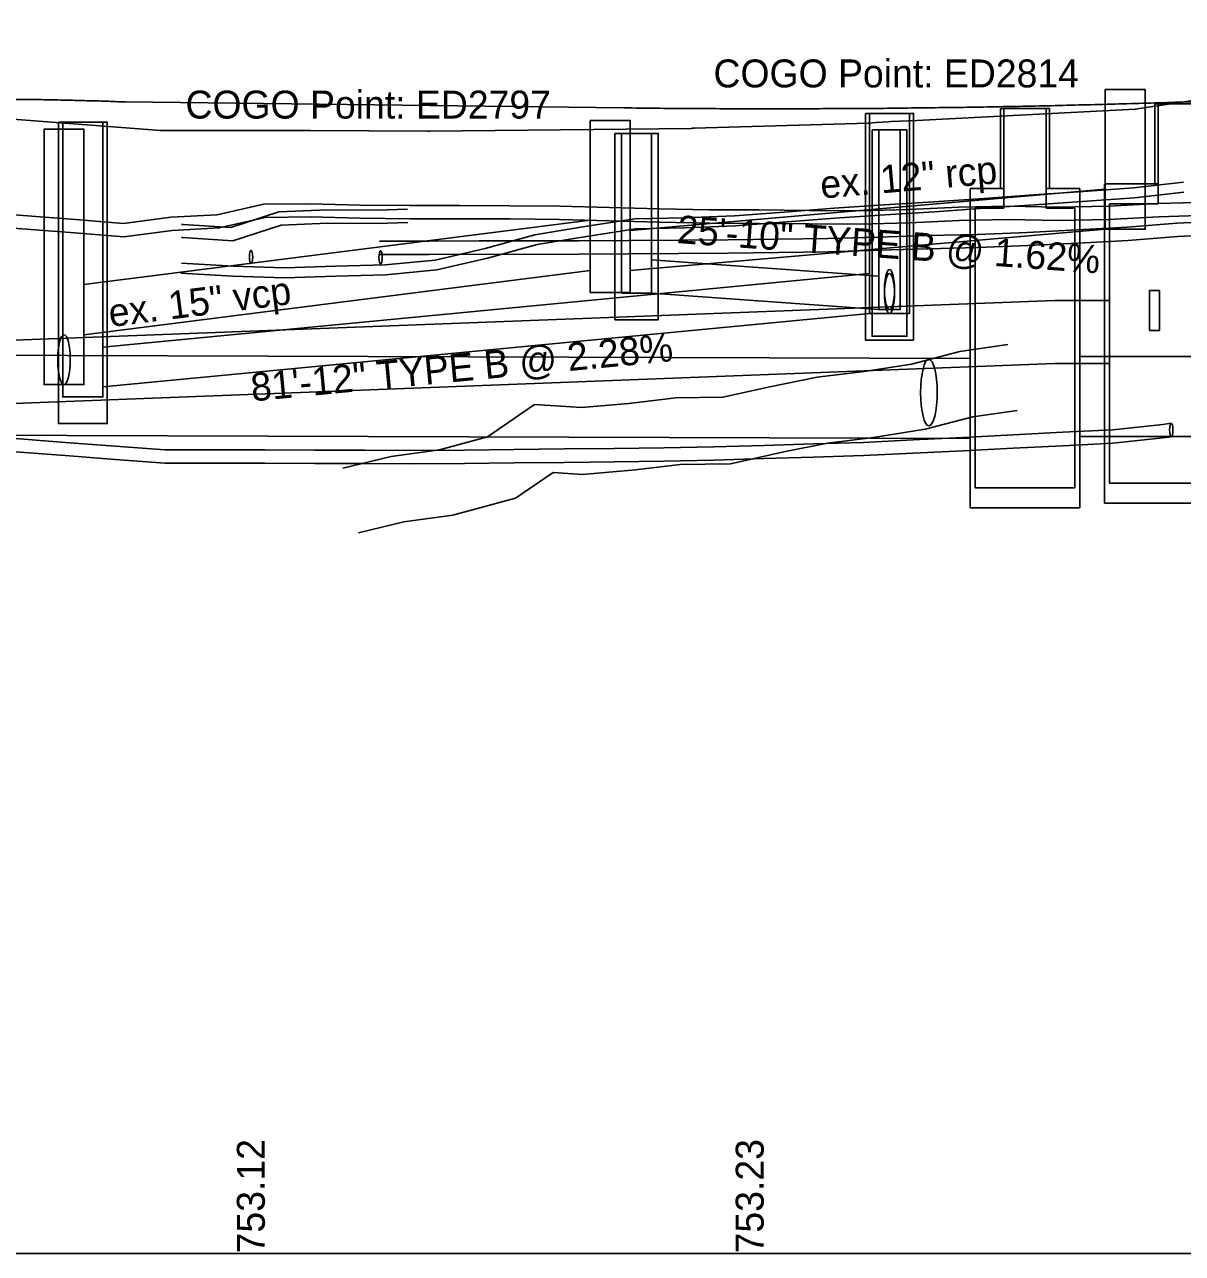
# Model space of a CAD drawing. Extents: x 1833473 to 1837132, y 704683 to 706683.
# Drawn here: x 1834036.7 to 1834152.8, y 705682.6 to 705805.8 of the extents above; entities that cross this region are included whole.
import ezdxf

# ---------------------------------------------------------------- set-up
doc = ezdxf.new("R2010")
doc.units = 0
for name, color, linetype in [('DR_P_Text', 7, 'Continuous'), ('DR_X_Cells', 7, 'Continuous'), ('DR_X_Storm_Sewer', 7, 'Continuous'), ('DR_X_Text', 7, 'Continuous'), ('GK_Cells', 7, 'Continuous'), ('PF_P_Grade_Line', 7, 'Continuous'), ('PF_X_Ground_Line', 7, 'Continuous'), ('PF_X_Text', 7, 'Continuous'), ('SC_Scratch1', 7, 'Continuous'), ('UT_P_Electric', 7, 'Continuous'), ('UT_P_Telecom', 7, 'Continuous'), ('UT_X_Electric', 7, 'Continuous'), ('UT_X_Gas', 7, 'Continuous'), ('UT_X_Water', 7, 'Continuous')]:
    doc.layers.add(name, color=color, linetype=linetype)

msp = doc.modelspace()

# ---------------------------------------------------------------- linework, layer by layer
at = {"layer": 'DR_X_Cells'}
for points in [[(1834035.78, 705764.29), (1834040.78, 705763.9), (1834045.78, 705763.51), (1834050.78, 705763.15), (1834055.78, 705763.15), (1834060.78, 705763.14), (1834065.78, 705763.12), (1834070.78, 705763.11), (1834075.78, 705763.09), (1834080.78, 705763.13), (1834085.78, 705763.18), (1834090.78, 705763.24), (1834095.78, 705763.29), (1834100.78, 705763.34), (1834105.78, 705763.45), (1834110.78, 705763.6), (1834115.78, 705763.75), (1834120.78, 705763.9), (1834125.78, 705764.14), (1834130.78, 705764.4), (1834135.78, 705764.65), (1834140.78, 705764.91), (1834145.78, 705765.16), (1834150.78, 705765.7), (1834151.63, 705765.81)], [(1834035.78, 705762.95), (1834040.78, 705762.57), (1834045.78, 705762.18), (1834050.78, 705761.82), (1834055.78, 705761.82), (1834060.78, 705761.81), (1834065.78, 705761.79), (1834070.78, 705761.77), (1834075.78, 705761.75), (1834080.78, 705761.8), (1834085.78, 705761.85), (1834090.78, 705761.9), (1834095.78, 705761.96), (1834100.78, 705762.01), (1834105.78, 705762.11), (1834110.78, 705762.27), (1834115.78, 705762.42), (1834120.78, 705762.57), (1834125.78, 705762.81), (1834130.78, 705763.06), (1834135.78, 705763.32), (1834140.78, 705763.57), (1834145.78, 705763.83), (1834150.78, 705764.36), (1834151.63, 705764.47)]]:
    msp.add_lwpolyline(points, dxfattribs=at)
msp.add_ellipse((1834151.63, 705765.14), major_axis=(0, 0.667), ratio=0.25, dxfattribs=at)
at = {"layer": 'DR_X_Storm_Sewer'}
for p, q in [((1834042.54, 705795.97), (1834042.54, 705795.97)), ((1834097.4, 705785.14), (1834145.02, 705789.26)), ((1834042.65, 705779.73), (1834093.4, 705786.17)), ((1834097.4, 705781.13), (1834145.02, 705785.25)), ((1834099.54, 705782.18), (1834122.31, 705780.54)), ((1834042.65, 705774.69), (1834093.4, 705781.13)), ((1834121.39, 705780.81), (1834044.56, 705773.45)), ((1834099.54, 705778.85), (1834122.31, 705777.21)), ((1834121.39, 705776.81), (1834044.56, 705769.45))]:
    msp.add_line(p, q, dxfattribs=at)
for points in [[(1834147.02, 705799.25), (1834145.02, 705799.25), (1834145.02, 705785.25), (1834149.02, 705785.25), (1834149.02, 705799.25), (1834147.02, 705799.25)], [(1834120.97, 705796.85), (1834120.97, 705774.14), (1834125.81, 705774.14), (1834125.81, 705796.85), (1834120.97, 705796.85)], [(1834121.39, 705796.85), (1834121.39, 705776.81), (1834125.39, 705776.81), (1834125.39, 705796.85)], [(1834040.65, 705795.29), (1834038.65, 705795.29), (1834038.65, 705769.69), (1834042.65, 705769.69), (1834042.65, 705795.29), (1834040.65, 705795.29)], [(1834040.1, 705795.97), (1834040.1, 705765.78), (1834044.98, 705765.78), (1834044.98, 705795.97), (1834040.1, 705795.97)], [(1834040.52, 705795.97), (1834040.52, 705768.45), (1834044.56, 705768.45), (1834044.56, 705795.97)], [(1834095.4, 705796.13), (1834093.4, 705796.13), (1834093.4, 705778.93), (1834097.4, 705778.93), (1834097.4, 705796.13), (1834095.4, 705796.13)], [(1834121.64, 705795.21), (1834121.64, 705774.54), (1834125.14, 705774.54), (1834125.14, 705795.21), (1834121.64, 705795.21)], [(1834122.31, 705795.21), (1834122.31, 705777.21), (1834124.47, 705777.21), (1834124.47, 705795.21)], [(1834095.87, 705794.85), (1834095.87, 705776.18), (1834100.21, 705776.18), (1834100.21, 705794.85), (1834095.87, 705794.85)], [(1834096.54, 705794.85), (1834096.54, 705778.85), (1834099.54, 705778.85), (1834099.54, 705794.85)]]:
    msp.add_lwpolyline(points, dxfattribs=at)
for centre, major_axis in [((1834123.39, 705779.21), (0, 2)), ((1834123.39, 705778.81), (0, 2)), ((1834040.65, 705772.19), (0, 2.5))]:
    msp.add_ellipse(centre, major_axis=major_axis, ratio=0.25, dxfattribs=at)
at = {"layer": 'GK_Cells'}
msp.add_line((1833710.78, 705682.65), (1834910.78, 705682.65), dxfattribs=at)
msp.add_line((1833710.78, 705682.65), (1834910.78, 705682.65), dxfattribs=at)
at = {"layer": 'PF_P_Grade_Line'}
msp.add_line((1834046.78, 705798.01), (1834096.78, 705797.41), dxfattribs=at)
for points in [[(1834096.78, 705797.41), (1834099.98, 705797.37), (1834103.18, 705797.35), (1834106.38, 705797.33), (1834109.58, 705797.32), (1834112.78, 705797.32), (1834115.98, 705797.33), (1834119.18, 705797.34), (1834122.38, 705797.36), (1834125.58, 705797.4), (1834128.78, 705797.44), (1834131.98, 705797.48), (1834135.18, 705797.54), (1834138.38, 705797.6), (1834141.58, 705797.68), (1834144.78, 705797.76), (1834147.98, 705797.85), (1834151.18, 705797.94), (1834154.38, 705798.05), (1834157.58, 705798.16), (1834160.78, 705798.28), (1834163.98, 705798.41), (1834167.18, 705798.55), (1834170.38, 705798.7), (1834173.58, 705798.85), (1834176.78, 705799.02), (1834179.98, 705799.19), (1834183.18, 705799.37), (1834186.38, 705799.55), (1834189.58, 705799.75), (1834192.78, 705799.95), (1834195.98, 705800.16), (1834199.18, 705800.39), (1834202.38, 705800.61), (1834205.58, 705800.85), (1834208.78, 705801.1), (1834211.98, 705801.35), (1834215.18, 705801.61), (1834218.38, 705801.88), (1834221.58, 705802.16), (1834224.78, 705802.44), (1834227.98, 705802.74), (1834231.18, 705803.04), (1834234.38, 705803.35), (1834237.58, 705803.67), (1834240.78, 705804), (1834243.98, 705804.33), (1834247.18, 705804.68), (1834250.38, 705805.03), (1834253.58, 705805.39), (1834256.78, 705805.76)], [(1833998.78, 705796.77), (1833999.74, 705796.85), (1834000.7, 705796.94), (1834001.66, 705797.02), (1834002.62, 705797.09), (1834003.58, 705797.17), (1834004.54, 705797.24), (1834005.5, 705797.31), (1834006.46, 705797.38), (1834007.42, 705797.44), (1834008.38, 705797.51), (1834009.34, 705797.57), (1834010.3, 705797.62), (1834011.26, 705797.68), (1834012.22, 705797.73), (1834013.18, 705797.78), (1834014.14, 705797.83), (1834015.1, 705797.88), (1834016.06, 705797.92), (1834017.02, 705797.96), (1834017.98, 705798), (1834018.94, 705798.03), (1834019.9, 705798.07), (1834020.86, 705798.1), (1834021.82, 705798.13), (1834022.78, 705798.15), (1834023.74, 705798.18), (1834024.7, 705798.2), (1834025.66, 705798.22), (1834026.62, 705798.23), (1834027.58, 705798.25), (1834028.54, 705798.26), (1834029.5, 705798.27), (1834030.46, 705798.27), (1834031.42, 705798.28), (1834032.38, 705798.28), (1834033.34, 705798.28), (1834034.3, 705798.28), (1834035.26, 705798.27), (1834036.22, 705798.26), (1834037.18, 705798.25), (1834038.14, 705798.24), (1834039.1, 705798.22), (1834040.06, 705798.2), (1834041.02, 705798.18), (1834041.98, 705798.16), (1834042.94, 705798.13), (1834043.9, 705798.11), (1834044.86, 705798.08), (1834045.82, 705798.04), (1834046.78, 705798.01)]]:
    msp.add_spline(points, degree=3, dxfattribs=at)
at = {"layer": 'PF_X_Ground_Line'}
msp.add_lwpolyline([(1834023.29, 705797.22), (1834050.31, 705795.15), (1834050.32, 705795.15), (1834050.34, 705795.15), (1834050.36, 705795.15), (1834050.38, 705795.15), (1834050.39, 705795.15), (1834050.4, 705795.15), (1834050.41, 705795.15), (1834050.43, 705795.15), (1834050.46, 705795.15), (1834050.49, 705795.15), (1834050.52, 705795.15), (1834050.54, 705795.15), (1834065.28, 705795.13), (1834077.13, 705795.08), (1834077.14, 705795.08), (1834077.15, 705795.08), (1834077.17, 705795.08), (1834077.19, 705795.08), (1834077.21, 705795.08), (1834077.24, 705795.08), (1834077.27, 705795.09), (1834077.3, 705795.09), (1834077.32, 705795.09), (1834103.54, 705795.36), (1834103.58, 705795.37), (1834103.7, 705795.37), (1834103.82, 705795.38), (1834121.28, 705795.89), (1834122.04, 705795.94), (1834123.26, 705796.01), (1834123.57, 705796.03), (1834124.38, 705796.07), (1834126.12, 705796.16), (1834148, 705797.28), (1834154.25, 705798.22)], dxfattribs=at)
at = {"layer": 'UT_P_Electric'}
for p, q in [((1834149.99, 705789.8), (1834149.99, 705797.8)), ((1834149.99, 705797.8), (1834154.91, 705797.8)), ((1834150.32, 705787.8), (1834150.32, 705797.8)), ((1834144.95, 705757.8), (1834144.95, 705789.8)), ((1834144.95, 705789.8), (1834150.32, 705789.8)), ((1834145.45, 705759.8), (1834145.45, 705787.8)), ((1834145.45, 705787.8), (1834150.32, 705787.8)), ((1834150.45, 705779.12), (1834149.44, 705779.12)), ((1834149.44, 705775.12), (1834149.44, 705779.12)), ((1834150.45, 705779.12), (1834150.45, 705775.12)), ((1833958.33, 705771.16), (1834139.95, 705778.12)), ((1834145.45, 705778.12), (1834139.95, 705778.12)), ((1834150.45, 705775.12), (1834149.44, 705775.12)), ((1833958.33, 705764.83), (1834139.95, 705771.79)), ((1834145.45, 705771.79), (1834139.95, 705771.79)), ((1834159.45, 705759.8), (1834145.45, 705759.8)), ((1834159.95, 705757.8), (1834144.95, 705757.8))]:
    msp.add_line(p, q, dxfattribs=at)
at = {"layer": 'UT_P_Telecom'}
for p, q in [((1834134.51, 705789.35), (1834134.51, 705797.35)), ((1834134.51, 705797.35), (1834139.43, 705797.35)), ((1834134.84, 705787.35), (1834134.84, 705797.35)), ((1834139.09, 705787.35), (1834139.09, 705797.35)), ((1834139.43, 705789.35), (1834139.43, 705797.35)), ((1834131.47, 705757.35), (1834131.47, 705789.35)), ((1834131.47, 705789.35), (1834134.84, 705789.35)), ((1834139.09, 705789.35), (1834142.47, 705789.35)), ((1834142.47, 705789.35), (1834142.47, 705757.35)), ((1834131.97, 705759.35), (1834131.97, 705787.35)), ((1834131.97, 705787.35), (1834134.84, 705787.35)), ((1834139.09, 705787.35), (1834141.97, 705787.35)), ((1834141.97, 705787.35), (1834141.97, 705759.35)), ((1834142.47, 705772.5), (1834175.78, 705772.5)), ((1834142.47, 705764.5), (1834175.78, 705764.5)), ((1834141.97, 705759.35), (1834131.97, 705759.35)), ((1834142.47, 705757.35), (1834131.47, 705757.35))]:
    msp.add_line(p, q, dxfattribs=at)
for points in [[(1833910.78, 705760.34), (1834010.78, 705772.69), (1834131.47, 705772.3)], [(1833910.78, 705752.34), (1834010.78, 705764.69), (1834131.47, 705764.3)]]:
    msp.add_lwpolyline(points, dxfattribs=at)
at = {"layer": 'UT_X_Electric'}
for points in [[(1834032.22, 705786.96), (1834037.01, 705786.59), (1834041.81, 705786.22), (1834046.61, 705785.82), (1834051.35, 705786.45), (1834056.02, 705786.71), (1834060.65, 705787.77), (1834065.34, 705787.81), (1834070.34, 705787.68), (1834075.34, 705787.63), (1834080.34, 705787.63), (1834085.34, 705787.61), (1834090.34, 705787.56), (1834095.34, 705787.43), (1834100.34, 705787.29), (1834105.34, 705787.2), (1834110.34, 705787.18), (1834115.34, 705787.13), (1834120.34, 705787.09), (1834125.34, 705787.22), (1834130.34, 705787.47), (1834135.33, 705787.55), (1834140.33, 705787.47), (1834145.33, 705787.57), (1834150.32, 705787.83), (1834155.32, 705787.98)], [(1834032.12, 705785.63), (1834036.91, 705785.26), (1834041.7, 705784.9), (1834046.64, 705784.48), (1834051.48, 705785.13), (1834056.21, 705785.38), (1834060.81, 705786.44), (1834065.33, 705786.48), (1834070.32, 705786.35), (1834075.34, 705786.3), (1834080.34, 705786.3), (1834085.33, 705786.28), (1834090.32, 705786.23), (1834100.31, 705785.96), (1834105.33, 705785.87), (1834110.33, 705785.84), (1834120.35, 705785.76), (1834125.39, 705785.89), (1834130.38, 705786.13), (1834135.33, 705786.22), (1834140.33, 705786.13), (1834145.38, 705786.24), (1834150.38, 705786.49), (1834155.36, 705786.65)], [(1834052.43, 705785.74), (1834052.58, 705785.74), (1834057.39, 705785.43), (1834062.2, 705786.99), (1834067.05, 705787.19), (1834072.02, 705787.17), (1834075.08, 705787.26)], [(1834052.44, 705784.41), (1834052.54, 705784.41), (1834057.56, 705784.08), (1834062.43, 705785.67), (1834067.08, 705785.86), (1834072.04, 705785.84), (1834075.12, 705785.93)], [(1834072.26, 705784.07), (1834077.25, 705784.07), (1834082.25, 705784.08), (1834087.24, 705784.09), (1834092.24, 705784.1), (1834097.23, 705784.13), (1834102.23, 705784.16), (1834107.22, 705784.2), (1834112.22, 705784.25), (1834117.21, 705784.33), (1834122.21, 705784.47), (1834127.2, 705784.61), (1834132.2, 705784.74), (1834137.2, 705784.94), (1834142.2, 705785.19), (1834147.2, 705785.47), (1834152.2, 705785.86), (1834157.2, 705786.08)], [(1834072.26, 705782.73), (1834077.25, 705782.73), (1834092.24, 705782.77), (1834097.24, 705782.79), (1834102.24, 705782.83), (1834107.23, 705782.87), (1834112.23, 705782.91), (1834117.24, 705783), (1834122.24, 705783.14), (1834132.24, 705783.41), (1834137.26, 705783.61), (1834142.27, 705783.86), (1834147.29, 705784.14), (1834152.28, 705784.52), (1834157.25, 705784.75)]]:
    msp.add_lwpolyline(points, dxfattribs=at)
for centre in [(1834059.4, 705782.47), (1834072.39, 705782.43)]:
    msp.add_ellipse(centre, major_axis=(0, -0.667), ratio=0.250004, dxfattribs=at)
at = {"layer": 'UT_X_Gas'}
for points in [[(1834052.37, 705780.85), (1834057.56, 705780.56), (1834062.76, 705780.37), (1834067.89, 705780.55), (1834072.91, 705780.68), (1834078.01, 705781.17), (1834083.1, 705782.34), (1834088.07, 705783.72), (1834093.01, 705784.53), (1834097.94, 705785.28), (1834102.88, 705785.39), (1834107.91, 705785.59), (1834117.92, 705786.37), (1834122.91, 705786.71), (1834127.91, 705787.01), (1834132.92, 705787.35), (1834137.92, 705787.69), (1834147.94, 705788.39), (1834152.89, 705788.96)], [(1834052.43, 705781.85), (1834057.6, 705781.56), (1834062.76, 705781.37), (1834067.86, 705781.55), (1834072.85, 705781.67), (1834077.85, 705782.16), (1834082.85, 705783.31), (1834087.85, 705784.69), (1834092.85, 705785.52), (1834097.85, 705786.28), (1834102.85, 705786.39), (1834107.85, 705786.58), (1834112.85, 705786.97), (1834117.85, 705787.36), (1834122.85, 705787.71), (1834127.85, 705788), (1834132.85, 705788.34), (1834137.85, 705788.69), (1834142.85, 705789.04), (1834147.85, 705789.39), (1834152.85, 705789.97)]]:
    msp.add_lwpolyline(points, dxfattribs=at)
at = {"layer": 'UT_X_Water'}
for points in [[(1834068.6, 705761.31), (1834073.45, 705762.49), (1834078.29, 705763.16), (1834083.1, 705764.44), (1834087.81, 705767.68), (1834092.53, 705767.38), (1834097.25, 705767.79), (1834101.97, 705768.36), (1834106.69, 705768.42), (1834111.41, 705769.47), (1834116.13, 705770.42), (1834120.85, 705770.99), (1834125.61, 705771.75), (1834130.43, 705773.01), (1834135.26, 705773.7)], [(1834070.17, 705754.83), (1834074.7, 705755.93), (1834079.62, 705756.62), (1834085.92, 705758.3), (1834089.68, 705760.88), (1834092.61, 705760.69), (1834097.94, 705761.16), (1834102.42, 705761.7), (1834107.47, 705761.76), (1834112.79, 705762.95), (1834117.19, 705763.83), (1834121.78, 705764.39), (1834126.98, 705765.22), (1834131.75, 705766.47), (1834136.2, 705767.1)]]:
    msp.add_lwpolyline(points, dxfattribs=at)
msp.add_ellipse((1834127.34, 705768.89), major_axis=(0, -3.33), ratio=0.249999, dxfattribs=at)

# ---------------------------------------------------------------- texts
at = {"layer": 'DR_P_Text'}
for s, rotation, p in [('25\'-10" TYPE B @ 1.62%', 355.8798, (1834102.04, 705783.87)), ('81\'-12" TYPE B @ 2.28%', 5.4722, (1834059.51, 705768))]:
    msp.add_text(s, height=2.8, rotation=rotation, dxfattribs=at).set_placement(p)
at = {"layer": 'DR_X_Text'}
for s, rotation, p in [('ex. 12" rcp', 4.9452, (1834116.57, 705788.32)), ('ex. 15" vcp', 7.2322, (1834045.3, 705775.45))]:
    msp.add_text(s, height=2.8, rotation=rotation, dxfattribs=at).set_placement(p)
at = {"layer": 'PF_X_Text'}
for s, p in [('753.12', (1834060.78, 705682.65)), ('753.23', (1834110.78, 705682.65))]:
    msp.add_text(s, height=2.8, rotation=90, dxfattribs=at).set_placement(p)
at = {"layer": 'SC_Scratch1'}
for s, p in [('COGO Point: ED2814', (1834105.75, 705799.46)), ('COGO Point: ED2797', (1834052.83, 705796.34))]:
    msp.add_text(s, height=2.8, dxfattribs=at).set_placement(p)

doc.saveas('drawing.dxf')
